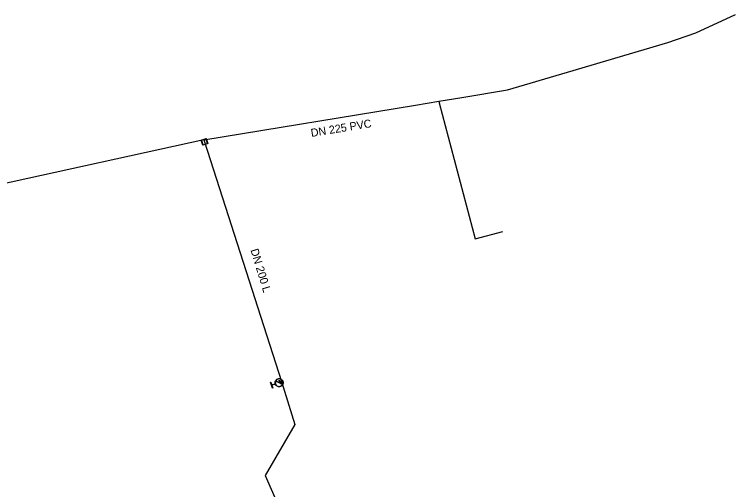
# Model space of a CAD drawing. Extents: x -832382 to -831581, y -1074670 to -1074251.
# Drawn here: x -831789.8 to -831609.7, y -1074369.6 to -1074251.1 of the extents above; entities that cross this region are included whole.
import ezdxf

# ---------------------------------------------------------------- set-up
doc = ezdxf.new("R2010")
doc.units = 0
for name, color, linetype in [('Hyd-odbočka', 7, 'Continuous'), ('Hyd-šoupě', 7, 'Continuous'), ('Hydrant', 7, 'Continuous'), ('Přípojka vodovodu', 7, 'Continuous'), ('Roz-řad', 7, 'Continuous'), ('Roz-řad-popis základní', 7, 'Continuous'), ('Šachta vodovodní', 7, 'Continuous')]:
    doc.layers.add(name, color=color, linetype=linetype)

msp = doc.modelspace()

# ---------------------------------------------------------------- linework, layer by layer
at = {"layer": 'Hyd-odbočka'}
for p, q in [((-831723.41, -1074342.82), (-831723.68, -1074342.98)), ((-831723.12, -1074342.71), (-831723.41, -1074342.82))]:
    msp.add_line(p, q, dxfattribs=at)
at = {"layer": 'Hyd-šoupě'}
msp.add_lwpolyline([(-831723.17, -1074343.26), (-831723.68, -1074342.4), (-831723.65, -1074342.38), (-831723.14, -1074343.24), (-831723.17, -1074343.26)], dxfattribs=at)
at = {"layer": 'Hydrant'}
for points in [[(-831724.62, -1074343.32), (-831725.51, -1074343.61), (-831725.28, -1074344.33), (-831725.34, -1074344.35), (-831725.82, -1074342.86), (-831725.76, -1074342.84), (-831725.53, -1074343.55), (-831724.64, -1074343.26)], [(-831722.86, -1074343.43), (-831724.53, -1074342.58)], [(-831724.5, -1074342.53), (-831722.83, -1074343.38)]]:
    msp.add_lwpolyline(points, dxfattribs=at)
for points in [[(-831724.64, -1074343.26), (-831724.71, -1074343.03), (-831724.66, -1074342.78), (-831724.61, -1074342.52), (-831724.43, -1074342.31), (-831724.24, -1074342.11), (-831723.99, -1074342.03), (-831723.74, -1074341.95), (-831723.48, -1074342), (-831723.21, -1074342.05), (-831723.01, -1074342.24), (-831722.81, -1074342.42), (-831722.73, -1074342.67), (-831722.65, -1074342.92), (-831722.7, -1074343.18), (-831722.75, -1074343.45), (-831722.94, -1074343.65), (-831723.12, -1074343.85), (-831723.37, -1074343.93), (-831723.62, -1074344.01), (-831723.89, -1074343.96), (-831724.16, -1074343.91), (-831724.35, -1074343.72), (-831724.54, -1074343.55), (-831724.62, -1074343.32)], [(-831724.53, -1074342.58), (-831724.58, -1074342.68), (-831724.6, -1074342.8), (-831724.64, -1074343.05), (-831724.57, -1074343.27), (-831724.5, -1074343.5), (-831724.31, -1074343.67), (-831724.13, -1074343.85), (-831723.87, -1074343.9), (-831723.62, -1074343.95), (-831723.39, -1074343.87), (-831723.16, -1074343.79), (-831722.98, -1074343.61), (-831722.91, -1074343.53), (-831722.86, -1074343.43)], [(-831722.83, -1074343.38), (-831722.78, -1074343.28), (-831722.76, -1074343.17), (-831722.71, -1074342.92), (-831722.79, -1074342.69), (-831722.87, -1074342.46), (-831723.05, -1074342.28), (-831723.24, -1074342.11), (-831723.49, -1074342.06), (-831723.74, -1074342.01), (-831723.97, -1074342.09), (-831724.21, -1074342.17), (-831724.38, -1074342.36), (-831724.45, -1074342.44), (-831724.5, -1074342.53)]]:
    msp.add_open_spline(points, degree=3, dxfattribs=at)
at = {"layer": 'Přípojka vodovodu'}
msp.add_lwpolyline([(-831683.83, -1074272.79), (-831683.73, -1074273.17), (-831674.71, -1074307.12), (-831667.79, -1074305.31)], dxfattribs=at)
at = {"layer": 'Roz-řad'}
for q in [(-831856.5, -1074307.38), (-831742.33, -1074282.89)]:
    msp.add_line((-831742.48, -1074282.37), q, dxfattribs=at)
for points in [[(-831742.48, -1074282.37), (-831689.65, -1074273.74), (-831683.83, -1074272.79), (-831678.02, -1074271.84), (-831666.61, -1074269.97), (-831651.64, -1074265.52), (-831626.58, -1074258.13), (-831619.6, -1074255.74), (-831609.7, -1074251.12)], [(-831742.33, -1074282.89), (-831723.12, -1074342.71), (-831719.79, -1074353.38), (-831727.12, -1074366.13), (-831711.35, -1074402.16)]]:
    msp.add_lwpolyline(points, dxfattribs=at)
at = {"layer": 'Šachta vodovodní'}
for points in [[(-831741.51, -1074283.32), (-831742.76, -1074283.7), (-831743.14, -1074282.46), (-831741.89, -1074282.08), (-831741.51, -1074283.32)], [(-831741.92, -1074282.13), (-831743.08, -1074282.49), (-831742.73, -1074283.65), (-831741.56, -1074283.3), (-831741.92, -1074282.13)]]:
    msp.add_lwpolyline(points, dxfattribs=at)

# ---------------------------------------------------------------- texts
at = {"layer": 'Roz-řad-popis základní'}
for s, rotation, p in [('DN 225 PVC', 9.2837, (-831715.6, -1074281.69)), ('DN 200 L', 286.9227, (-831730.84, -1074309.89))]:
    msp.add_text(s, height=2, rotation=rotation, dxfattribs=at).set_placement(p)

doc.saveas('drawing.dxf')
